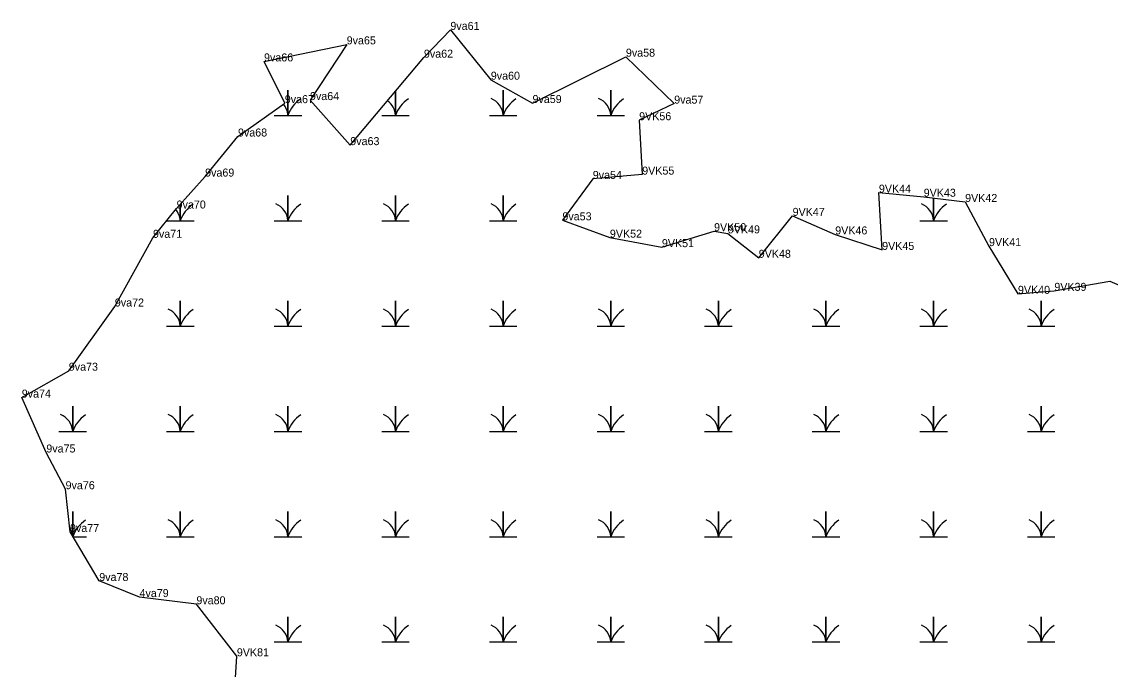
# Model space of a CAD drawing. Extents: x 2072529 to 2268796, y 436423 to 470397.
# Drawn here: x 2205378 to 2206058, y 447371 to 447776 of the extents above; entities that cross this region are included whole.
import ezdxf

# ---------------------------------------------------------------- set-up
doc = ezdxf.new("R2010")
doc.units = 0
for name, color, linetype in [('Exist Environmental Wetland Boundary', 7, 'Continuous'), ('Exist Environmental Wetland Boundary Cogo Comment', 7, 'Continuous'), ('Exist Environmental Wetland Boundary Cogo Point CELL', 7, 'Continuous'), ('Exist Hydro Swamp or Marsh', 7, 'Continuous')]:
    doc.layers.add(name, color=color, linetype=linetype)

msp = doc.modelspace()

# ---------------------------------------------------------------- linework, layer by layer
at = {"layer": 'Exist Environmental Wetland Boundary'}
msp.add_lwpolyline([(2205510.77, 447349.31), (2205512.65, 447379.36), (2205487.36, 447411.84), (2205451.82, 447416.34), (2205426.66, 447426.39), (2205408.39, 447457.01), (2205405.62, 447483.71), (2205393.57, 447506.66), (2205378.23, 447540.94), (2205407.63, 447557.75), (2205436.4, 447597.85), (2205460.24, 447640.77), (2205475, 447659.07), (2205492.82, 447679.03), (2205513.35, 447704.06), (2205542.6, 447724.9), (2205529.62, 447750.97), (2205581.29, 447761.62), (2205558.36, 447726.81), (2205583.54, 447698.66), (2205629.56, 447753.31), (2205646.08, 447770.65), (2205671.35, 447739.54), (2205697.41, 447724.96), (2205755.78, 447753.91), (2205785.96, 447724.59), (2205764.06, 447714.24), (2205765.96, 447680.26), (2205735.07, 447677.54), (2205716.1, 447651.71), (2205745.76, 447640.87), (2205778.27, 447634.94), (2205810.88, 447644.92), (2205819.49, 447643.55), (2205838.8, 447628.3), (2205859.97, 447654.47), (2205886.58, 447642.89), (2205915.92, 447633.2), (2205913.88, 447668.99), (2205941.88, 447666.43), (2205967.77, 447663.16), (2205982.69, 447635.6), (2206000.77, 447605.78), (2206023.52, 447607.64), (2206058.3, 447613.74), (2206094.42, 447598.03)], dxfattribs=at)
at = {"layer": 'Exist Environmental Wetland Boundary Cogo Point CELL'}
for p, q in [((2205646.08, 447770.65), (2205646.08, 447770.65)), ((2205646.08, 447770.65), (2205646.08, 447770.65)), ((2205581.29, 447761.62), (2205581.29, 447761.62)), ((2205581.29, 447761.62), (2205581.29, 447761.62)), ((2205629.56, 447753.31), (2205629.56, 447753.31)), ((2205629.56, 447753.31), (2205629.56, 447753.31)), ((2205755.78, 447753.91), (2205755.78, 447753.91)), ((2205755.78, 447753.91), (2205755.78, 447753.91)), ((2205529.62, 447750.97), (2205529.62, 447750.97)), ((2205529.62, 447750.97), (2205529.62, 447750.97)), ((2205671.35, 447739.54), (2205671.35, 447739.54)), ((2205671.35, 447739.54), (2205671.35, 447739.54)), ((2205542.6, 447724.9), (2205542.6, 447724.9)), ((2205542.6, 447724.9), (2205542.6, 447724.9)), ((2205558.36, 447726.81), (2205558.36, 447726.81)), ((2205558.36, 447726.81), (2205558.36, 447726.81)), ((2205697.41, 447724.96), (2205697.41, 447724.96)), ((2205697.41, 447724.96), (2205697.41, 447724.96)), ((2205785.96, 447724.59), (2205785.96, 447724.59)), ((2205785.96, 447724.59), (2205785.96, 447724.59)), ((2205764.06, 447714.24), (2205764.06, 447714.24)), ((2205513.35, 447704.06), (2205513.35, 447704.06)), ((2205513.35, 447704.06), (2205513.35, 447704.06)), ((2205583.54, 447698.66), (2205583.54, 447698.66)), ((2205583.54, 447698.66), (2205583.54, 447698.66)), ((2205492.82, 447679.03), (2205492.82, 447679.03)), ((2205492.82, 447679.03), (2205492.82, 447679.03)), ((2205735.07, 447677.54), (2205735.07, 447677.54)), ((2205735.07, 447677.54), (2205735.07, 447677.54)), ((2205765.96, 447680.26), (2205765.96, 447680.26)), ((2205913.88, 447668.99), (2205913.88, 447668.99)), ((2205941.88, 447666.43), (2205941.88, 447666.43)), ((2205475, 447659.07), (2205475, 447659.07)), ((2205475, 447659.07), (2205475, 447659.07)), ((2205967.77, 447663.16), (2205967.77, 447663.16)), ((2205716.1, 447651.71), (2205716.1, 447651.71)), ((2205716.1, 447651.71), (2205716.1, 447651.71)), ((2205859.97, 447654.47), (2205859.97, 447654.47)), ((2205810.88, 447644.92), (2205810.88, 447644.92)), ((2205819.49, 447643.55), (2205819.49, 447643.55)), ((2205460.24, 447640.77), (2205460.24, 447640.77)), ((2205460.24, 447640.77), (2205460.24, 447640.77)), ((2205745.76, 447640.87), (2205745.76, 447640.87)), ((2205886.58, 447642.89), (2205886.58, 447642.89)), ((2205778.27, 447634.94), (2205778.27, 447634.94)), ((2205915.92, 447633.2), (2205915.92, 447633.2)), ((2205982.69, 447635.6), (2205982.69, 447635.6)), ((2205838.8, 447628.3), (2205838.8, 447628.3)), ((2206058.3, 447613.74), (2206058.3, 447613.74)), ((2206000.77, 447605.78), (2206000.77, 447605.78)), ((2206023.52, 447607.64), (2206023.52, 447607.64)), ((2205436.4, 447597.85), (2205436.4, 447597.85)), ((2205407.63, 447557.75), (2205407.63, 447557.75)), ((2205378.23, 447540.94), (2205378.23, 447540.94)), ((2205393.57, 447506.66), (2205393.57, 447506.66)), ((2205393.57, 447506.66), (2205393.57, 447506.66)), ((2205405.62, 447483.71), (2205405.62, 447483.71)), ((2205405.62, 447483.71), (2205405.62, 447483.71)), ((2205408.39, 447457.01), (2205408.39, 447457.01)), ((2205408.39, 447457.01), (2205408.39, 447457.01)), ((2205426.66, 447426.39), (2205426.66, 447426.39)), ((2205426.66, 447426.39), (2205426.66, 447426.39)), ((2205451.82, 447416.34), (2205451.82, 447416.34)), ((2205451.82, 447416.34), (2205451.82, 447416.34)), ((2205487.36, 447411.84), (2205487.36, 447411.84)), ((2205487.36, 447411.84), (2205487.36, 447411.84)), ((2205512.65, 447379.36), (2205512.65, 447379.36))]:
    msp.add_line(p, q, dxfattribs=at)
at = {"layer": 'Exist Hydro Swamp or Marsh'}
for points in [[(2205535.97, 447717.28), (2205544.57, 447717.28), (2205544.57, 447733.07), (2205544.57, 447717.28), (2205553.17, 447717.28)], [(2205603.22, 447717.28), (2205611.82, 447717.28), (2205611.82, 447732.24)], [(2205611.82, 447732.24), (2205611.82, 447717.28), (2205620.42, 447717.28)], [(2205670.47, 447717.28), (2205679.07, 447717.28), (2205679.07, 447733.07), (2205679.07, 447717.28), (2205687.67, 447717.28)], [(2205737.72, 447717.28), (2205746.32, 447717.28), (2205746.32, 447733.07), (2205746.32, 447717.28), (2205754.92, 447717.28)], [(2205535.97, 447651.48), (2205544.57, 447651.48), (2205544.57, 447667.27), (2205544.57, 447651.48), (2205553.17, 447651.48)], [(2205603.22, 447651.48), (2205611.82, 447651.48), (2205611.82, 447667.27), (2205611.82, 447651.48), (2205620.42, 447651.48)], [(2205670.47, 447651.48), (2205679.07, 447651.48), (2205679.07, 447667.27), (2205679.07, 447651.48), (2205687.67, 447651.48)], [(2205939.47, 447651.48), (2205948.07, 447651.48), (2205948.07, 447665.65)], [(2205948.07, 447665.65), (2205948.07, 447651.48), (2205956.67, 447651.48)], [(2205468.88, 447651.48), (2205477.32, 447651.48), (2205477.32, 447661.67)], [(2205477.32, 447661.67), (2205477.32, 447651.48), (2205485.92, 447651.48)], [(2205468.72, 447585.68), (2205477.32, 447585.68), (2205477.32, 447601.47), (2205477.32, 447585.68), (2205485.92, 447585.68)], [(2205535.97, 447585.68), (2205544.57, 447585.68), (2205544.57, 447601.47), (2205544.57, 447585.68), (2205553.17, 447585.68)], [(2205603.22, 447585.68), (2205611.82, 447585.68), (2205611.82, 447601.47), (2205611.82, 447585.68), (2205620.42, 447585.68)], [(2205670.47, 447585.68), (2205679.07, 447585.68), (2205679.07, 447601.47), (2205679.07, 447585.68), (2205687.67, 447585.68)], [(2205737.72, 447585.68), (2205746.32, 447585.68), (2205746.32, 447601.47), (2205746.32, 447585.68), (2205754.92, 447585.68)], [(2205804.97, 447585.68), (2205813.57, 447585.68), (2205813.57, 447601.47), (2205813.57, 447585.68), (2205822.17, 447585.68)], [(2205872.22, 447585.68), (2205880.82, 447585.68), (2205880.82, 447601.47), (2205880.82, 447585.68), (2205889.42, 447585.68)], [(2205939.47, 447585.68), (2205948.07, 447585.68), (2205948.07, 447601.47), (2205948.07, 447585.68), (2205956.67, 447585.68)], [(2206006.72, 447585.68), (2206015.32, 447585.68), (2206015.32, 447601.47), (2206015.32, 447585.68), (2206023.92, 447585.68)], [(2205401.47, 447519.88), (2205410.07, 447519.88), (2205410.07, 447535.67), (2205410.07, 447519.88), (2205418.67, 447519.88)], [(2205468.72, 447519.88), (2205477.32, 447519.88), (2205477.32, 447535.67), (2205477.32, 447519.88), (2205485.92, 447519.88)], [(2205535.97, 447519.88), (2205544.57, 447519.88), (2205544.57, 447535.67), (2205544.57, 447519.88), (2205553.17, 447519.88)], [(2205603.22, 447519.88), (2205611.82, 447519.88), (2205611.82, 447535.67), (2205611.82, 447519.88), (2205620.42, 447519.88)], [(2205670.47, 447519.88), (2205679.07, 447519.88), (2205679.07, 447535.67), (2205679.07, 447519.88), (2205687.67, 447519.88)], [(2205737.72, 447519.88), (2205746.32, 447519.88), (2205746.32, 447535.67), (2205746.32, 447519.88), (2205754.92, 447519.88)], [(2205804.97, 447519.88), (2205813.57, 447519.88), (2205813.57, 447535.67), (2205813.57, 447519.88), (2205822.17, 447519.88)], [(2205872.22, 447519.88), (2205880.82, 447519.88), (2205880.82, 447535.67), (2205880.82, 447519.88), (2205889.42, 447519.88)], [(2205939.47, 447519.88), (2205948.07, 447519.88), (2205948.07, 447535.67), (2205948.07, 447519.88), (2205956.67, 447519.88)], [(2206006.72, 447519.88), (2206015.32, 447519.88), (2206015.32, 447535.67), (2206015.32, 447519.88), (2206023.92, 447519.88)], [(2205410.07, 447454.2), (2205410.07, 447469.87), (2205410.07, 447454.2)], [(2205468.72, 447454.08), (2205477.32, 447454.08), (2205477.32, 447469.87), (2205477.32, 447454.08), (2205485.92, 447454.08)], [(2205535.97, 447454.08), (2205544.57, 447454.08), (2205544.57, 447469.87), (2205544.57, 447454.08), (2205553.17, 447454.08)], [(2205603.22, 447454.08), (2205611.82, 447454.08), (2205611.82, 447469.87), (2205611.82, 447454.08), (2205620.42, 447454.08)], [(2205670.47, 447454.08), (2205679.07, 447454.08), (2205679.07, 447469.87), (2205679.07, 447454.08), (2205687.67, 447454.08)], [(2205737.72, 447454.08), (2205746.32, 447454.08), (2205746.32, 447469.87), (2205746.32, 447454.08), (2205754.92, 447454.08)], [(2205804.97, 447454.08), (2205813.57, 447454.08), (2205813.57, 447469.87), (2205813.57, 447454.08), (2205822.17, 447454.08)], [(2205872.22, 447454.08), (2205880.82, 447454.08), (2205880.82, 447469.87), (2205880.82, 447454.08), (2205889.42, 447454.08)], [(2205939.47, 447454.08), (2205948.07, 447454.08), (2205948.07, 447469.87), (2205948.07, 447454.08), (2205956.67, 447454.08)], [(2206006.72, 447454.08), (2206015.32, 447454.08), (2206015.32, 447469.87), (2206015.32, 447454.08), (2206023.92, 447454.08)], [(2205410.13, 447454.08), (2205418.67, 447454.08)], [(2205535.97, 447388.28), (2205544.57, 447388.28), (2205544.57, 447404.07), (2205544.57, 447388.28), (2205553.17, 447388.28)], [(2205603.22, 447388.28), (2205611.82, 447388.28), (2205611.82, 447404.07), (2205611.82, 447388.28), (2205620.42, 447388.28)], [(2205670.47, 447388.28), (2205679.07, 447388.28), (2205679.07, 447404.07), (2205679.07, 447388.28), (2205687.67, 447388.28)], [(2205737.72, 447388.28), (2205746.32, 447388.28), (2205746.32, 447404.07), (2205746.32, 447388.28), (2205754.92, 447388.28)], [(2205804.97, 447388.28), (2205813.57, 447388.28), (2205813.57, 447404.07), (2205813.57, 447388.28), (2205822.17, 447388.28)], [(2205872.22, 447388.28), (2205880.82, 447388.28), (2205880.82, 447404.07), (2205880.82, 447388.28), (2205889.42, 447388.28)], [(2205939.47, 447388.28), (2205948.07, 447388.28), (2205948.07, 447404.07), (2205948.07, 447388.28), (2205956.67, 447388.28)], [(2206006.72, 447388.28), (2206015.32, 447388.28), (2206015.32, 447404.07), (2206015.32, 447388.28), (2206023.92, 447388.28)]]:
    msp.add_lwpolyline(points, dxfattribs=at)
for centre, radius, start, end in [((2205562.81, 447711.22), 19.22, 122.12745, 161.62219), ((2205599.55, 447716.4), 12.3, 4.14034, 53.72422), ((2205630.06, 447711.22), 19.22, 122.12745, 161.62219), ((2205666.8, 447716.4), 12.3, 4.14034, 67.53497), ((2205697.31, 447711.22), 19.22, 122.12745, 161.62219), ((2205734.05, 447716.4), 12.3, 4.14034, 67.53497), ((2205764.56, 447711.22), 19.22, 122.12745, 161.62219), ((2205532.3, 447716.4), 12.3, 4.14034, 39.89299), ((2205465.05, 447650.6), 12.3, 4.14034, 39.74793), ((2205495.56, 447645.42), 19.22, 122.12745, 161.62219), ((2205532.3, 447650.6), 12.3, 4.14034, 67.53497), ((2205562.81, 447645.42), 19.22, 122.12745, 161.62219), ((2205599.55, 447650.6), 12.3, 4.14034, 67.53497), ((2205630.06, 447645.42), 19.22, 122.12745, 161.62219), ((2205666.8, 447650.6), 12.3, 4.14034, 67.53497), ((2205697.31, 447645.42), 19.22, 122.12745, 161.62219), ((2205935.8, 447650.6), 12.3, 4.14034, 67.53497), ((2205966.31, 447645.42), 19.22, 122.12745, 161.62219), ((2205465.05, 447584.8), 12.3, 4.14034, 67.53497), ((2205495.56, 447579.62), 19.22, 122.12745, 161.62219), ((2205532.3, 447584.8), 12.3, 4.14034, 67.53497), ((2205562.81, 447579.62), 19.22, 122.12745, 161.62219), ((2205599.55, 447584.8), 12.3, 4.14034, 67.53497), ((2205630.06, 447579.62), 19.22, 122.12745, 161.62219), ((2205666.8, 447584.8), 12.3, 4.14034, 67.53497), ((2205697.31, 447579.62), 19.22, 122.12745, 161.62219), ((2205734.05, 447584.8), 12.3, 4.14034, 67.53497), ((2205764.56, 447579.62), 19.22, 122.12745, 161.62219), ((2205801.3, 447584.8), 12.3, 4.14034, 67.53497), ((2205831.81, 447579.62), 19.22, 122.12745, 161.62219), ((2205868.55, 447584.8), 12.3, 4.14034, 67.53497), ((2205899.06, 447579.62), 19.22, 122.12745, 161.62219), ((2205935.8, 447584.8), 12.3, 4.14034, 67.53497), ((2205966.31, 447579.62), 19.22, 122.12745, 161.62219), ((2206003.05, 447584.8), 12.3, 4.14034, 67.53497), ((2206033.56, 447579.62), 19.22, 122.12745, 161.62219), ((2205397.8, 447519), 12.3, 4.14034, 67.53497), ((2205428.31, 447513.82), 19.22, 122.12745, 161.62219), ((2205465.05, 447519), 12.3, 4.14034, 67.53497), ((2205495.56, 447513.82), 19.22, 122.12745, 161.62219), ((2205532.3, 447519), 12.3, 4.14034, 67.53497), ((2205562.81, 447513.82), 19.22, 122.12745, 161.62219), ((2205599.55, 447519), 12.3, 4.14034, 67.53497), ((2205630.06, 447513.82), 19.22, 122.12745, 161.62219), ((2205666.8, 447519), 12.3, 4.14034, 67.53497), ((2205697.31, 447513.82), 19.22, 122.12745, 161.62219), ((2205734.05, 447519), 12.3, 4.14034, 67.53497), ((2205764.56, 447513.82), 19.22, 122.12745, 161.62219), ((2205801.3, 447519), 12.3, 4.14034, 67.53497), ((2205831.81, 447513.82), 19.22, 122.12745, 161.62219), ((2205868.55, 447519), 12.3, 4.14034, 67.53497), ((2205899.06, 447513.82), 19.22, 122.12745, 161.62219), ((2205935.8, 447519), 12.3, 4.14034, 67.53497), ((2205966.31, 447513.82), 19.22, 122.12745, 161.62219), ((2206003.05, 447519), 12.3, 4.14034, 67.53497), ((2206033.56, 447513.82), 19.22, 122.12745, 161.62219), ((2205397.8, 447453.2), 12.3, 4.74284, 33.24958), ((2205428.31, 447448.02), 19.22, 122.12745, 161.39626), ((2205465.05, 447453.2), 12.3, 4.14034, 67.53497), ((2205495.56, 447448.02), 19.22, 122.12745, 161.62219), ((2205532.3, 447453.2), 12.3, 4.14034, 67.53497), ((2205562.81, 447448.02), 19.22, 122.12745, 161.62219), ((2205599.55, 447453.2), 12.3, 4.14034, 67.53497), ((2205630.06, 447448.02), 19.22, 122.12745, 161.62219), ((2205666.8, 447453.2), 12.3, 4.14034, 67.53497), ((2205697.31, 447448.02), 19.22, 122.12745, 161.62219), ((2205734.05, 447453.2), 12.3, 4.14034, 67.53497), ((2205764.56, 447448.02), 19.22, 122.12745, 161.62219), ((2205801.3, 447453.2), 12.3, 4.14034, 67.53497), ((2205831.81, 447448.02), 19.22, 122.12745, 161.62219), ((2205868.55, 447453.2), 12.3, 4.14034, 67.53497), ((2205899.06, 447448.02), 19.22, 122.12745, 161.62219), ((2205935.8, 447453.2), 12.3, 4.14034, 67.53497), ((2205966.31, 447448.02), 19.22, 122.12745, 161.62219), ((2206003.05, 447453.2), 12.3, 4.14034, 67.53497), ((2206033.56, 447448.02), 19.22, 122.12745, 161.62219), ((2205532.3, 447387.4), 12.3, 4.14034, 67.53497), ((2205562.81, 447382.22), 19.22, 122.12745, 161.62219), ((2205599.55, 447387.4), 12.3, 4.14034, 67.53497), ((2205630.06, 447382.22), 19.22, 122.12745, 161.62219), ((2205666.8, 447387.4), 12.3, 4.14034, 67.53497), ((2205697.31, 447382.22), 19.22, 122.12745, 161.62219), ((2205734.05, 447387.4), 12.3, 4.14034, 67.53497), ((2205764.56, 447382.22), 19.22, 122.12745, 161.62219), ((2205801.3, 447387.4), 12.3, 4.14034, 67.53497), ((2205831.81, 447382.22), 19.22, 122.12745, 161.62219), ((2205868.55, 447387.4), 12.3, 4.14034, 67.53497), ((2205899.06, 447382.22), 19.22, 122.12745, 161.62219), ((2205935.8, 447387.4), 12.3, 4.14034, 67.53497), ((2205966.31, 447382.22), 19.22, 122.12745, 161.62219), ((2206003.05, 447387.4), 12.3, 4.14034, 67.53497), ((2206033.56, 447382.22), 19.22, 122.12745, 161.62219)]:
    msp.add_arc(centre, radius, start, end, dxfattribs=at)

# ---------------------------------------------------------------- texts
at = {"layer": 'Exist Environmental Wetland Boundary Cogo Comment'}
for s, p in [('9va61', (2205646.08, 447770.65)), ('9va65', (2205581.29, 447761.62)), ('9va58', (2205755.78, 447753.91)), ('9va66', (2205529.62, 447750.97)), ('9va62', (2205629.56, 447753.31)), ('9va60', (2205671.35, 447739.54)), ('9va64', (2205558.36, 447726.81)), ('9va67', (2205542.6, 447724.9)), ('9va59', (2205697.41, 447724.96)), ('9va57', (2205785.96, 447724.59)), ('9VK56', (2205764.06, 447714.24)), ('9va68', (2205513.35, 447704.06)), ('9va63', (2205583.54, 447698.66)), ('9va69', (2205492.82, 447679.03)), ('9VK55', (2205765.96, 447680.26)), ('9va54', (2205735.07, 447677.54)), ('9VK44', (2205913.88, 447668.99)), ('9VK43', (2205941.88, 447666.43)), ('9va70', (2205475, 447659.07)), ('9VK42', (2205967.77, 447663.16)), ('9va53', (2205716.1, 447651.71)), ('9VK47', (2205859.97, 447654.47)), ('9VK50', (2205810.88, 447644.92)), ('9va71', (2205460.24, 447640.77)), ('9VK52', (2205745.76, 447640.87)), ('9VK49', (2205819.49, 447643.55)), ('9VK46', (2205886.58, 447642.89)), ('9VK51', (2205778.27, 447634.94)), ('9VK45', (2205915.92, 447633.2)), ('9VK41', (2205982.69, 447635.6)), ('9VK48', (2205838.8, 447628.3)), ('9VK40', (2206000.77, 447605.78)), ('9VK39', (2206023.52, 447607.64)), ('9va72', (2205436.4, 447597.85)), ('9va73', (2205407.63, 447557.75)), ('9va74', (2205378.23, 447540.94)), ('9va75', (2205393.57, 447506.66)), ('9va76', (2205405.62, 447483.71)), ('9va77', (2205408.39, 447457.01)), ('9va78', (2205426.66, 447426.39)), ('4va79', (2205451.82, 447416.34)), ('9va80', (2205487.36, 447411.84)), ('9VK81', (2205512.65, 447379.36))]:
    msp.add_text(s, height=5, dxfattribs=at).set_placement(p)

doc.saveas('drawing.dxf')
